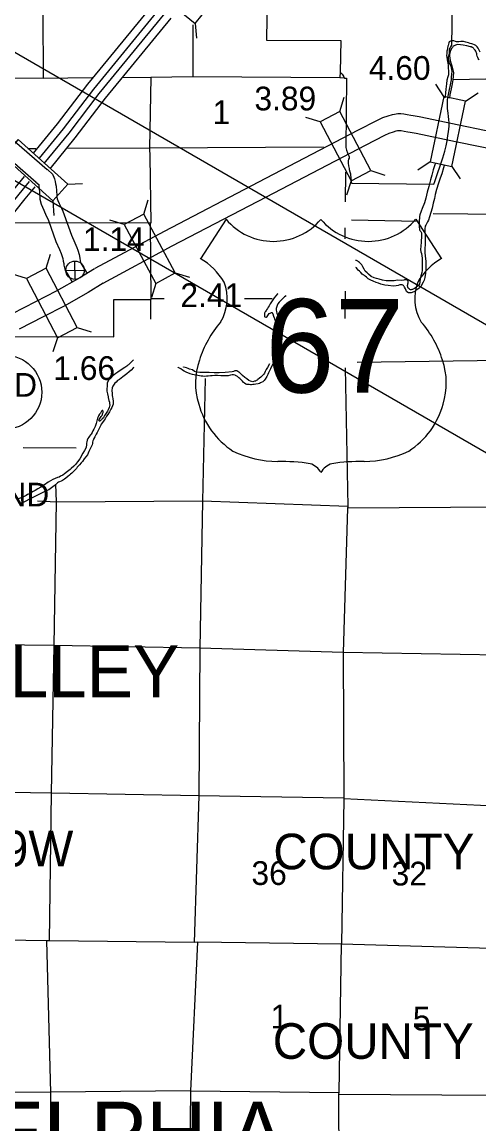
# Model space of a CAD drawing. Extents: x 369523 to 838377, y 495025 to 936819.
# Drawn here: x 601784 to 618049, y 785066 to 824276 of the extents above; entities that cross this region are included whole.
import ezdxf

# ---------------------------------------------------------------- set-up
doc = ezdxf.new("R2010")
doc.units = 0
for name, color, linetype in [('21', 7, 'Continuous'), ('6', 7, 'Continuous'), ('DSN_BRDG_Annotation', 7, 'Continuous'), ('DSN_DRFT_Common-Annotations', 7, 'Continuous'), ('DSN_DRFT_Common-Line', 7, 'Continuous'), ('DSN_DRFT_Junk-No-Plot', 7, 'Continuous'), ('Level 1', 7, 'Continuous'), ('Level 10', 7, 'Continuous'), ('Level 11', 7, 'Continuous'), ('Level 15', 7, 'Continuous'), ('Level 2', 7, 'Continuous'), ('Level 21', 7, 'Continuous'), ('Level 22', 7, 'Continuous'), ('Level 23', 7, 'Continuous'), ('Level 6', 7, 'Continuous')]:
    doc.layers.add(name, color=color, linetype=linetype)

msp = doc.modelspace()

# ---------------------------------------------------------------- linework, layer by layer
at = {"layer": '21'}
for p, q in [((459282, 905322), (715348, 757482)), ((708796, 756692), (471020, 893972))]:
    msp.add_line(p, q, dxfattribs=at)
at = {"layer": '6'}
for p, q in [((609045, 817260), (608137, 815854)), ((615801, 817260), (616710, 815854))]:
    msp.add_line(p, q, dxfattribs=at)
for centre, radius, start, end in [((610737, 818683), 2211, 220.075, 319.6701), ((614109, 818683), 2211, 220.3299, 319.925), ((606949, 813814), 2361, 30.7809, 59.9883), ((617897, 813814), 2361, 120.0117, 149.2191), ((607469, 814437), 1618, 328.8105, 21.2108), ((617378, 814437), 1618, 158.7892, 211.1895), ((611701, 811120), 3776, 138.9565, 162.6913), ((613146, 811120), 3776, 17.3087, 41.0435), ((610454, 811429), 2495, 160.9576, 197.3819), ((614392, 811429), 2495, 342.6181, 19.0424), ((610860, 811436), 2887, 195.1074, 237.1312), ((613986, 811436), 2887, 302.8688, 344.8926), ((610914, 812345), 3707, 244.0771, 269.5779), ((613932, 812345), 3707, 270.4221, 295.9229), ((611000, 801850), 6790, 81.1942, 90.9539), ((611849, 807937), 651, 28.0342, 72.9864), ((612998, 807937), 651, 107.0136, 151.9658), ((613847, 801850), 6790, 89.0461, 98.8058)]:
    msp.add_arc(centre, radius, start, end, dxfattribs=at)
at = {"layer": 'DSN_DRFT_Common-Annotations'}
for p, q in [((603679, 815119), (603664, 815770)), ((603346, 815437), (603997, 815452))]:
    msp.add_line(p, q, dxfattribs=at)
msp.add_circle((603671, 815445), 326, dxfattribs=at)
at = {"layer": 'DSN_DRFT_Common-Line'}
msp.add_circle((601167, 811103), 1320, dxfattribs=at)
at = {"layer": 'Level 1'}
for points in [[(601331, 820203), (602679, 819030)], [(600937, 819750), (602285, 818577)], [(602687, 819023), (602863, 818859), (602919, 818760), (602943, 818697), (602967, 818602), (602978, 818515), (602993, 818431), (603019, 818098), (603020, 818050), (603036, 817985), (603064, 817920), (603105, 817821), (603184, 817650), (603241, 817545), (603286, 817421), (603550, 816691), (603669, 816414), (603734, 816257), (603769, 816158), (603817, 816009), (603843, 815871), (603859, 815773), (603866, 815718), (603871, 815696), (603908, 815634), (604073, 815358)], [(602278, 818584), (602376, 818492), (602377, 818489), (602385, 818425), (602397, 818356), (602419, 818069), (602421, 817972), (602464, 817797), (602511, 817686), (602556, 817579), (602647, 817381), (602692, 817298), (602722, 817217), (602991, 816470), (603116, 816182), (603173, 816042), (603201, 815965), (603234, 815861), (603252, 815767), (603266, 815685), (603274, 815619), (603292, 815531), (603325, 815439), (603394, 815325), (603561, 815045)]]:
    msp.add_lwpolyline(points, dxfattribs=at)
at = {"layer": 'Level 10'}
for points in [[(618097, 823205), (618045, 823300), (618016, 823351), (617981, 823397), (617933, 823438), (617890, 823463), (617828, 823490), (617791, 823505), (617735, 823518), (617677, 823539), (617627, 823552), (617585, 823565), (617498, 823579), (617435, 823582), (617403, 823581), (617335, 823572), (617293, 823571), (617249, 823574), (617211, 823587), (617155, 823602), (617102, 823611), (617055, 823604), (616992, 823567), (616980, 823541), (616967, 823489), (616958, 823446), (616945, 823418), (616932, 823348), (616917, 823279), (616910, 823241), (616902, 823151), (616899, 823087), (616916, 822939), (616926, 822857), (616937, 822809), (616948, 822745), (616955, 822691), (616968, 822477), (616964, 822433), (616965, 822401), (616943, 822323), (616911, 822204), (616896, 822074), (616866, 821887), (616860, 821756), (616845, 821638), (616838, 821582)], [(618055, 822936), (618046, 822947), (618022, 822983), (618007, 823009), (617988, 823060), (617973, 823106), (617968, 823146), (617960, 823178), (617947, 823206), (617933, 823235), (617908, 823275), (617889, 823299), (617871, 823320), (617849, 823344), (617826, 823366), (617802, 823375), (617766, 823392), (617750, 823398), (617623, 823426), (617485, 823451), (617395, 823467), (617301, 823473), (617249, 823466), (617215, 823457), (617188, 823443), (617162, 823432), (617136, 823418), (617103, 823375), (617068, 823338), (617039, 823280), (617023, 823213), (617004, 823131), (616996, 823071), (617009, 822987), (617029, 822903), (617048, 822825), (617072, 822754), (617121, 822573), (617139, 822481), (617134, 822355), (617119, 822216), (617097, 822078), (617065, 821905), (617016, 821680), (617005, 821562)], [(616488, 819229), (616424, 819015), (616366, 818833), (616320, 818658), (616262, 818423), (616211, 818220), (616159, 818014), (616106, 817841), (616027, 817637), (615991, 817543), (615947, 817420), (615937, 817353), (615932, 817299), (615921, 817215), (615918, 817169), (615918, 817105), (615916, 817061), (615922, 816975), (615927, 816943), (615930, 816907), (615936, 816881), (615946, 816859), (615973, 816831), (615975, 816821), (615998, 816776), (616005, 816746), (616009, 816706), (616008, 816664), (615989, 816443), (615974, 816301), (615970, 816185), (615984, 816101), (615999, 816043), (616013, 815953), (616026, 815873), (616031, 815821), (616030, 815761), (616030, 815697), (616031, 815623), (616027, 815543), (616023, 815439), (616014, 815367), (615985, 815240), (615959, 815127), (615939, 815047), (615933, 814939), (615855, 814867), (615845, 814861), (615813, 814836), (615786, 814813), (615758, 814793), (615729, 814778), (615705, 814768), (615679, 814761), (615655, 814753), (615637, 814750), (615612, 814748), (615591, 814762), (615567, 814781), (615532, 814808), (615516, 814836), (615507, 814896), (615514, 814938), (615517, 814964), (615527, 814992), (615532, 815021), (615534, 815047), (615523, 815067), (615517, 815072), (615507, 815078), (615491, 815090), (615463, 815097), (615397, 815098), (615375, 815092), (615301, 815076), (615155, 815087), (615026, 815065), (614978, 815066), (614872, 815064), (614746, 815073), (614616, 815096), (614492, 815128), (614401, 815152), (614313, 815177), (614208, 815226), (614111, 815301), (614066, 815352), (614001, 815413), (613958, 815482), (613916, 815561), (613878, 815640), (613830, 815689), (613797, 815721)], [(616809, 819166), (616786, 819086), (616727, 818873), (616672, 818717), (616613, 818546), (616540, 818318), (616494, 818137), (616469, 817999), (616424, 817827), (616378, 817648), (616339, 817501), (616294, 817340), (616251, 817225), (616218, 817163), (616152, 817053), (616135, 817007), (616119, 816920), (616119, 816840), (616135, 816698), (616138, 816554), (616132, 816354), (616125, 816228), (616122, 816066), (616132, 815958)], [(613797, 815721), (613764, 815748), (613738, 815766), (613686, 815785), (613653, 815786)], [(616132, 815958), (616154, 815750), (616160, 815654), (616162, 815558), (616163, 815442), (616150, 815367), (616145, 815325), (616136, 815267), (616118, 815188), (616096, 815090), (616077, 815046), (616059, 815015), (616015, 814932), (615988, 814882), (615975, 814861), (615920, 814806), (615875, 814775), (615814, 814730), (615774, 814701), (615725, 814676), (615640, 814646), (615580, 814635), (615558, 814637), (615536, 814640), (615512, 814654), (615475, 814689), (615452, 814729), (615429, 814780), (615400, 814842), (615390, 814862), (615375, 814883), (615357, 814901), (615343, 814913), (615321, 814922), (615295, 814926), (615264, 814929), (615235, 814923), (615177, 814903), (615106, 814884), (614992, 814880), (614822, 814902), (614700, 814916), (614559, 814953), (614467, 814979), (614388, 815006), (614288, 815050), (614199, 815090), (614108, 815136), (614082, 815162), (614051, 815197), (614002, 815234), (613970, 815256), (613932, 815277), (613893, 815302), (613846, 815361), (613799, 815409), (613750, 815452), (613716, 815495), (613687, 815528), (613666, 815546)], [(610888, 814613), (610874, 814601), (610757, 814463), (610664, 814323), (610618, 814244), (610577, 814183), (610546, 814132), (610517, 814086), (610488, 814039), (610473, 814009), (610456, 813980), (610440, 813962), (610424, 813942), (610415, 813921), (610411, 813901), (610418, 813872), (610416, 813839), (610415, 813795), (610432, 813782), (610460, 813772), (610476, 813771), (610511, 813795), (610534, 813832), (610562, 813872), (610583, 813903), (610614, 813921), (610660, 813940), (610680, 813939), (610713, 813897), (610741, 813806), (610754, 813756), (610769, 813704), (610798, 813653), (610825, 813591), (610840, 813557)], [(611183, 814538), (611128, 814494), (611042, 814413), (610977, 814345), (610942, 814308), (610895, 814247), (610861, 814185)], [(610861, 814185), (610851, 814158), (610838, 814114), (610831, 814086), (610826, 814048), (610826, 814024), (610837, 813972), (610858, 813908), (610890, 813829), (610930, 813728), (610962, 813634), (610989, 813557), (610992, 813547)], [(605757, 812257), (605729, 812228), (605699, 812204), (605654, 812163), (605570, 812083), (605550, 812063), (605511, 812036), (605446, 811988), (605351, 811926), (605190, 811823), (605121, 811766), (605068, 811725), (605032, 811700), (604931, 811606), (604866, 811532), (604820, 811423), (604809, 811317), (604806, 811225), (604806, 811139), (604822, 811043), (604848, 810939), (604855, 810911), (604877, 810814), (604892, 810746), (604901, 810704), (604908, 810646), (604906, 810630), (604901, 810612), (604882, 810554), (604849, 810477), (604823, 810426), (604778, 810359), (604759, 810325), (604724, 810276), (604697, 810222), (604681, 810193)], [(610706, 812111), (610701, 812093), (610692, 812069), (610628, 811938), (610555, 811794), (610529, 811731), (610496, 811667), (610440, 811571), (610399, 811517), (610382, 811496), (610350, 811472), (610301, 811449), (610267, 811432), (610238, 811415), (610188, 811398), (610110, 811385), (610045, 811379), (609995, 811374), (609951, 811369), (609911, 811369), (609873, 811376), (609845, 811377), (609791, 811382), (609745, 811395), (609702, 811423), (609672, 811454), (609629, 811497), (609590, 811542), (609566, 811566), (609539, 811591), (609503, 811617), (609489, 811629), (609448, 811662), (609428, 811673), (609387, 811703), (609365, 811714), (609317, 811721), (609265, 811722), (609209, 811705), (609122, 811689), (608988, 811685), (608864, 811692), (608742, 811696), (608645, 811696), (608555, 811690), (608487, 811681), (608405, 811677), (608348, 811672), (608270, 811668), (608218, 811675), (608164, 811678), (608046, 811694), (607969, 811712), (607857, 811738), (607771, 811758), (607626, 811818), (607561, 811850), (607493, 811893), (607436, 811936), (607347, 811986), (607324, 811998)], [(610595, 812117), (610593, 812111), (610520, 811987), (610475, 811912), (610441, 811844), (610414, 811779), (610381, 811730), (610359, 811712)], [(605599, 811835), (605512, 811761), (605471, 811723), (605367, 811646), (605251, 811560), (605186, 811515), (605131, 811466), (605086, 811425), (605061, 811386), (605016, 811315), (604993, 811265), (604981, 811170), (604987, 811064), (604997, 810982), (605006, 810930), (605017, 810885), (605027, 810779), (605026, 810727), (605025, 810681), (605006, 810614), (604980, 810560), (604945, 810495), (604897, 810410), (604835, 810310), (604796, 810250), (604742, 810162), (604713, 810104), (604680, 810075)], [(605764, 811990), (605756, 811983), (605672, 811891), (605599, 811835)], [(610359, 811712), (610324, 811669), (610279, 811634), (610236, 811601), (610179, 811556), (610153, 811538), (610120, 811521), (610090, 811502), (610056, 811492), (609997, 811478), (609915, 811497), (609862, 811520), (609783, 811578), (609710, 811631), (609633, 811695), (609523, 811803), (609501, 811823), (609432, 811860), (609362, 811862), (609313, 811841), (609265, 811826), (609016, 811801), (608800, 811797), (608623, 811793), (608447, 811804), (608407, 811805), (608287, 811801), (608201, 811801), (608111, 811803), (608007, 811813), (607927, 811846), (607852, 811898), (607747, 811928), (607697, 811947), (607641, 811968), (607587, 811983), (607536, 812000), (607533, 812005)], [(604681, 810193), (604639, 810158), (604625, 810138), (604613, 810126), (604587, 810105), (604563, 810083), (604549, 810071), (604533, 810069), (604521, 810093), (604525, 810111), (604533, 810131), (604555, 810171), (604576, 810203), (604602, 810235), (604614, 810251), (604630, 810274), (604646, 810302), (604652, 810324), (604654, 810336), (604664, 810364), (604668, 810380), (604671, 810388), (604667, 810418), (604667, 810434), (604663, 810440), (604659, 810444), (604655, 810448), (604641, 810449), (604627, 810443), (604613, 810427), (604603, 810407), (604571, 810363), (604542, 810321), (604508, 810261), (604494, 810227), (604472, 810175), (604447, 810085), (604418, 809994), (604382, 809880), (604337, 809792), (604307, 809728), (604279, 809672), (604248, 809612), (604226, 809584), (604190, 809545), (604158, 809507), (604128, 809461), (604103, 809403), (604089, 809337), (604079, 809285), (604080, 809227), (604066, 809145), (604056, 809115), (604013, 809033), (603953, 808936), (603840, 808732), (603763, 808629), (603685, 808527), (603632, 808471), (603536, 808388), (603500, 808356), (603404, 808283), (603301, 808203), (603231, 808158), (603153, 808112), (603101, 808082), (603049, 808065), (602967, 808037), (602885, 807998), (602793, 807946), (602711, 807899), (602668, 807867), (602630, 807841), (602546, 807790), (602508, 807766), (602450, 807730), (602348, 807671), (602248, 807609), (602177, 807566), (602087, 807516), (602023, 807481), (601981, 807461), (601931, 807433), (601887, 807409), (601813, 807366), (601585, 807291)], [(604680, 810075), (604606, 809972), (604592, 809937), (604567, 809883), (604529, 809807), (604462, 809673), (604424, 809611), (604388, 809537), (604378, 809514), (604341, 809458), (604325, 809420), (604311, 809386), (604303, 809368), (604294, 809324), (604292, 809320), (604296, 809302), (604298, 809288), (604298, 809274), (604282, 809234), (604256, 809186), (604219, 809114), (604167, 808996), (604114, 808879), (603993, 808735), (603931, 808638), (603893, 808590), (603828, 808520), (603752, 808439), (603734, 808411), (603720, 808393), (603694, 808361), (603631, 808295), (603553, 808224), (603505, 808188), (603469, 808154), (603420, 808108), (603346, 808041), (603298, 808005), (603222, 807966), (603174, 807938), (603122, 807912), (603086, 807900), (603042, 807875), (603018, 807853), (602994, 807829), (602961, 807797), (602925, 807767), (602837, 807696), (602739, 807634), (602623, 807579), (602450, 807500), (602306, 807433), (602212, 807381), (602118, 807334), (602022, 807284), (601922, 807231), (601844, 807193), (601700, 807142)]]:
    msp.add_lwpolyline(points, dxfattribs=at)
at = {"layer": 'Level 11'}
for points in [[(619156, 820226), (617334, 820605), (615919, 820901), (615710, 820934), (615626, 820953), (615496, 820971), (615377, 820998), (615268, 821007), (615159, 821008), (615044, 820990), (614959, 820973), (614811, 820932), (614617, 820863), (614429, 820776), (613725, 820422), (610200, 818577), (606841, 816825), (604376, 815502)], [(619030, 819640), (617212, 820017), (615811, 820310), (615596, 820345), (615519, 820362), (615389, 820380), (615284, 820404), (615240, 820407), (615205, 820408), (615149, 820399), (615095, 820388), (614993, 820360), (614845, 820307), (614690, 820235), (613998, 819888), (610477, 818045), (607122, 816295), (604660, 814973)], [(604362, 815494), (603837, 815174), (602996, 814698), (602263, 814315), (601429, 813894)], [(604674, 814981), (604140, 814657), (603283, 814171), (602537, 813782), (601681, 813349)]]:
    msp.add_lwpolyline(points, dxfattribs=at)
at = {"layer": 'Level 15'}
for points in [[(607858, 824182), (607862, 822322)], [(604283, 822285), (602548, 822267), (601017, 822274), (597259, 822443), (595760, 822433), (591904, 822430), (590377, 822417), (588577, 822412)], [(606363, 822306), (605347, 822296)], [(613257, 822284), (613100, 822288), (607862, 822322), (606363, 822306)], [(620810, 822273), (618849, 822243), (618292, 822242), (617136, 822225)], [(613296, 818931), (613287, 817877)], [(613280, 816955), (613279, 816567)], [(613282, 814698), (613280, 813731)], [(613283, 811970), (613379, 807039), (613368, 806973), (613214, 801846), (613236, 796659), (613237, 796629), (613155, 791467)], [(613035, 775994), (613088, 781052), (613088, 781090), (613062, 786121), (613067, 786185), (613155, 791467)]]:
    msp.add_lwpolyline(points, dxfattribs=at)
at = {"layer": 'Level 2'}
for points in [[(617089, 823458), (617110, 824913), (615791, 824932), (615830, 827540), (615868, 830221), (618516, 830158), (621156, 830137), (621209, 832680), (623882, 832646)], [(610569, 829234), (610551, 827645), (610491, 823628), (613131, 823623), (613114, 822492), (613177, 822427), (613207, 822385), (613240, 822327), (613258, 822279), (613328, 822279)], [(617066, 822217), (617077, 822327), (617085, 822416), (617090, 822514), (617088, 822582), (617075, 822642), (617054, 822697), (617019, 822763), (617007, 822785), (616992, 822824), (616986, 822859), (616979, 822923), (616968, 822962), (616966, 822991), (616966, 823011), (616969, 823044), (616976, 823072), (616995, 823156), (616999, 823213), (616997, 823305), (617007, 823332), (617024, 823365), (617044, 823397), (617089, 823458)], [(613328, 822279), (613308, 819806), (613334, 819717), (613370, 819620), (613399, 819562), (613420, 819512), (613429, 819479), (613429, 819454), (613423, 819432), (613407, 819394), (613400, 819371), (613395, 819348), (613391, 819314), (613389, 819290), (613390, 819255), (613405, 819155), (613423, 819063), (613432, 819024), (613454, 818943), (613469, 818909), (613476, 818878), (613481, 818841), (613483, 818731), (613498, 818642), (613504, 818598), (613508, 818547)], [(616968, 820379), (616981, 820462), (616989, 820571), (616989, 820688), (616981, 820813), (616968, 820914), (616947, 821037), (616940, 821120), (616932, 821195), (616927, 821307), (616927, 821406), (616932, 821495), (616942, 821578), (616963, 821703), (617066, 822217)], [(613508, 818547), (616446, 818504), (616482, 818607), (616763, 819445), (616836, 819686), (616880, 819866), (616914, 820053), (616942, 820225), (616968, 820379)], [(606355, 817131), (601032, 817116), (601024, 814401), (601019, 813081), (605048, 813079)], [(605048, 813079), (605055, 814399), (606375, 814398), (606355, 817131)]]:
    msp.add_lwpolyline(points, dxfattribs=at)
at = {"layer": 'Level 21'}
for p, q in [((607942, 824226), (607994, 823700)), ((616799, 821624), (616510, 822066)), ((613095, 821095), (613252, 821598)), ((617575, 821462), (618016, 821751)), ((612393, 820727), (611889, 820885)), ((616313, 819298), (615871, 819009)), ((617088, 819136), (617377, 818694)), ((614197, 818990), (614701, 818832)), ((603415, 818503), (603942, 818530)), ((613495, 818622), (613337, 818118)), ((606115, 817443), (606268, 817949)), ((602885, 817915), (602912, 817387)), ((605417, 817069), (604912, 817221)), ((602645, 815516), (602803, 816020)), ((601943, 815150), (601439, 815308)), ((607239, 815350), (607745, 815198)), ((606541, 814975), (606389, 814470)), ((603744, 813410), (604248, 813252)), ((603042, 813044), (602884, 812540))]:
    msp.add_line(p, q, dxfattribs=at)
for points in [[(608445, 824838), (606608, 826345), (606106, 825733), (607942, 824226)], [(616799, 821624), (616313, 819298), (617088, 819136), (617575, 821462)], [(614197, 818990), (613095, 821095), (612393, 820727), (613495, 818622)], [(603415, 818503), (601650, 820094), (601120, 819505), (602885, 817915)], [(605417, 817069), (606541, 814975), (607239, 815350), (606115, 817443)], [(601943, 815150), (603042, 813044), (603744, 813410), (602645, 815516)]]:
    msp.add_lwpolyline(points, close=True, dxfattribs=at)
at = {"layer": 'Level 22'}
for points in [[(602548, 822267), (602535, 824615)], [(606363, 822306), (606325, 819793), (606325, 819790)], [(613103, 822513), (613100, 822288)], [(602276, 819764), (601996, 819762)], [(606325, 819793), (603382, 819772)], [(612516, 819818), (606325, 819793)], [(606325, 819793), (606330, 819497)], [(606330, 819497), (606365, 817124)], [(615886, 817182), (613517, 817230)], [(628286, 817377), (624150, 817395), (618890, 817430), (616416, 817457)], [(606841, 814424), (606375, 814423)], [(610690, 814428), (609698, 814427)], [(606361, 814398), (606359, 813709)], [(634498, 811972), (634474, 811973), (629307, 812060), (624075, 812174), (618843, 812237), (613709, 812165)], [(608297, 811597), (608207, 807232), (608109, 801994), (608079, 796740), (607908, 791519)], [(603708, 809113), (601826, 809122)], [(602759, 791585), (602836, 796836), (602927, 802095), (603014, 807202), (602988, 807837)], [(608205, 807222), (603013, 807188), (602337, 807224)], [(613379, 807039), (608205, 807222)], [(633808, 806749), (629181, 806908), (623992, 807076), (618874, 807016), (613368, 806973)], [(608109, 801994), (602915, 802088), (597662, 802148), (594157, 802175)], [(632757, 801505), (629163, 801563), (623920, 801617), (618766, 801750), (613214, 801846), (608109, 801994)], [(608079, 796740), (602834, 796833), (597583, 796925), (592337, 796981)], [(613236, 796659), (608079, 796740)], [(632349, 796224), (629074, 796246), (623848, 796488), (618595, 796373), (613237, 796629)], [(602653, 791584), (602800, 786187), (602793, 780818), (602623, 776383)], [(608034, 791531), (607781, 786248), (607719, 780963), (607729, 779968)], [(607781, 786248), (602798, 786197), (597523, 786164), (595364, 786195)], [(607781, 786248), (613067, 786185)], [(613062, 786121), (618565, 786094), (623573, 786255), (623762, 786249)]]:
    msp.add_lwpolyline(points, dxfattribs=at)
at = {"layer": 'Level 23'}
for points in [[(606463, 824927), (604110, 822061)], [(606675, 824752), (604326, 821890)], [(606869, 824593), (604522, 821735)], [(607081, 824419), (604738, 821565)], [(604110, 822061), (603036, 820649), (602185, 819608)], [(604326, 821890), (603252, 820478), (602399, 819435)], [(604522, 821735), (603449, 820324), (602563, 819240)], [(604738, 821565), (603665, 820153), (602769, 819058)], [(601863, 818780), (601481, 818313), (600135, 816648), (598429, 814555), (597149, 813072), (596198, 812102), (595574, 811476), (595275, 811204)], [(602040, 818601), (601675, 818155), (600329, 816491), (598620, 814394), (597334, 812903), (596376, 811927), (595747, 811295), (595452, 811027)], [(602241, 818413), (601889, 817982), (600543, 816317), (598831, 814217), (597536, 812716), (596572, 811733), (595937, 811097), (595613, 810802)]]:
    msp.add_lwpolyline(points, dxfattribs=at)
at = {"layer": 'Level 6'}
for points in [[(607908, 791519), (602759, 791585), (602653, 791584), (597454, 791662)], [(607908, 791519), (602759, 791585), (602653, 791584), (597454, 791662)], [(624919, 791154), (623823, 791181), (623696, 791159), (618555, 791305), (618471, 791305), (613155, 791467), (608034, 791531), (607908, 791519)], [(624959, 791153), (623823, 791181), (623696, 791159), (618555, 791305), (618471, 791305), (613155, 791467), (608034, 791531), (607908, 791519)]]:
    msp.add_lwpolyline(points, dxfattribs=at)

# ---------------------------------------------------------------- texts
at = {"layer": '21'}
for s, p in [('R19W', (598902, 794234)), ('COUNTY', (610730, 794127)), ('COUNTY', (610709, 787383))]:
    msp.add_text(s, height=1267.2, dxfattribs=at).set_placement(p)
at = {"layer": '6'}
msp.add_text('67', height=3326.4, dxfattribs=at).set_placement((610438, 811092))
at = {"layer": 'DSN_BRDG_Annotation'}
for s, p in [('1.14', (603953, 816128)), ('80.60 END', (596793, 810942)), ('7.42 END', (597855, 807039))]:
    msp.add_text(s, height=844.8, dxfattribs=at).set_placement(p)
at = {"layer": 'DSN_DRFT_Common-Annotations'}
for s, height, p in [('CADDO VALLEY', 1848, (588432, 800250)), ('ARKADELPHIA', 2217.6, (590382, 783638))]:
    msp.add_text(s, height=height, dxfattribs=at).set_placement(p)
at = {"layer": 'DSN_DRFT_Junk-No-Plot'}
for s, p in [('4.60', (614127, 822219)), ('3.89', (610056, 821132)), ('2.41', (607421, 814133)), ('1.66', (602898, 811540))]:
    msp.add_text(s, height=844.8, dxfattribs=at).set_placement(p)
at = {"layer": 'Level 22'}
for s, height, p in [('1', 845, (608564, 820645)), ('36', 844.8, (609951, 793570)), ('32', 844.8, (614940, 793551)), ('1', 845, (610632, 788463)), ('5', 845, (615696, 788395))]:
    msp.add_text(s, height=height, dxfattribs=at).set_placement(p)

doc.saveas('drawing.dxf')
